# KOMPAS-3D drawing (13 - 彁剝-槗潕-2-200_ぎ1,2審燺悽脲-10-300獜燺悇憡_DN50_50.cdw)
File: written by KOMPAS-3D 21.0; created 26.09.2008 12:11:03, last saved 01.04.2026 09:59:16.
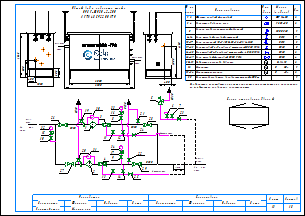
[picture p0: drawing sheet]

Sheets 1-2: A3, landscape

Document properties: Наименование: Макро:21; Автор: RaskoAdmin; Форматы листов документа: 2xA3; Полное имя файла: \\UR38nt01\Departments\КТО\КБ ПУРДГ\Заявки\Прайс-лист на типовые шкафы ГРПШ\ПРДГ_стандарт_20_03_2026\ПРДГ с РДСК\ПРДГ-ШУЭО-2-200_до1,2МПа_Рвых-10-300кПа_РДСК_DN50_50.cdw

Title block, sheet 1: Наименование: Пункт учета газа / ПУГ-Ш-400-Р / ЛГТИ.485922.001ТУ; designation: ЛГТИ.03.4411141; sheet number: 1; Количество листов документа: 2; organisation: ООО "ЭЛЬСТЕР Газэлектроника"; Форматы листов документа: A3; stored path: C:\Рабочие документы\Компас\ПУГ\Схема.cdw; Разработал: Устинов; Проверил: Кошкин; Утвердил: Кошкин
Title block, sheet 2: sheet number: 2; stored path: D:\Рабочие документы\Заявки\ПУРДГ\ПУРДГ-ШУЭО-2-100-Р 4411220.cdw; designation, second copy: ЛГТИ.03.4411141-

Views: Вид 1, Вид 2
Referenced files: wcvoit.frw
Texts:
  Normal
  Вход
  газа
  PDI
  Выход
  Р=     кПа
  DN50
  DN20
  Импульс DN20
  ≥5DN
  HYSWLongFangSong
  № на
  схеме
  Усл.
  обозн.
  Марка
  (модель)
  Кол.
  Фильтр газовый фланцевый
  ФГ 16-50
  Регулятор давления газа
  РДCК-50
  Клапан предохранительный сбросной
  КПС DN20
  Кран шаровой газовый латунный
  DN15
  Кран кнопочный VE-РАСКО-НЗ-1,6-G1/2-М20
  Кран шаровой "под приварку" штуцерный DN20 PN16
  Кран шаровой "под приварку" штуцерный п/п DN20 PN16
  Кран шаровой фланцевый DN50 PN16
  Индикатор перепада давления
  Delta 15
  Манометр
  Манометр-напоромер
  Электрообогреватель взрывозащищенный 400Вт
  0...     МПа
  0...     кПа
  Общий вид и габариты шкафа
  ПРДГ-ШУЭО-2-200
  Выход газа
  Вход газа
  Схема открывания дверей
  Р=       МПа
  logo-rasko-ge.png
  Предприятие изготовитель может заменять комплектующие на аналогичные,
  не ухудшающие заявленных характеристик.
  Должность
  Конструктор
  Фамилия
  Подпись
  Дата
  Согласовано
  Максимкин
  Лист
  Листов
  POLYLINE_STYLE_0.18_RGB_0_0_0
  POLYLINE_STYLE_0.50_RGB_0_0_0
  POLYLINE_STYLE_0.34_RGB_0_0_0
  PHANTOM_RGB_0_0_0_SC_1_THICK_0.18
  K5LT_THIN_RGB_0_0_0_THICK_0.18
  K5LT32769_RGB_0_0_0_THICK_0.18
  K5LT12_RGB_0_0_0_SC_1_THICK_0.18
  K5LT_DASHED_RGB_0_0_0_SC_1_THICK_0.18
  ACISOTGL_RGB_0_0_0_SC_0.8_THICK_0.25
  CONTINUOUS_RGB_0_127_31_THICK_0.3
  CONTINUOUS_RGB_0_0_255_THICK_0.35
  CONTINUOUS_RGB_255_0_0_THICK_0.35
  POLYLINE_STYLE_0.25_RGB_0_0_0
  CONTINUOUS_RGB_0_0_0_THICK_0.5
  POLYLINE_STYLE_0.35_RGB_0_0_255
  CONTINUOUS_RGB_0_0_0_THICK_0.4
  CONTINUOUS_RGB_0_0_0_THICK_0.35
  Без оформления
Dimensions and other numbers on the sheet: 1; 2; 3; 4; 5; 10; 27; 28; 29; 23; 8; 12; 19; 20; 21; 22; 25; 24; 30; 31; 15; 16; 26; 6; 7; 11; 14; 13; 33; 1, 2; 3, 4; 6-14; 9; 15-17; 19-23; 24-25; 26-29; 30-31; 32; 33-34; 35; 1000; 400; 1050; 500; 305; 2000; 4130; 1565; 2300; 17; 34; 18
